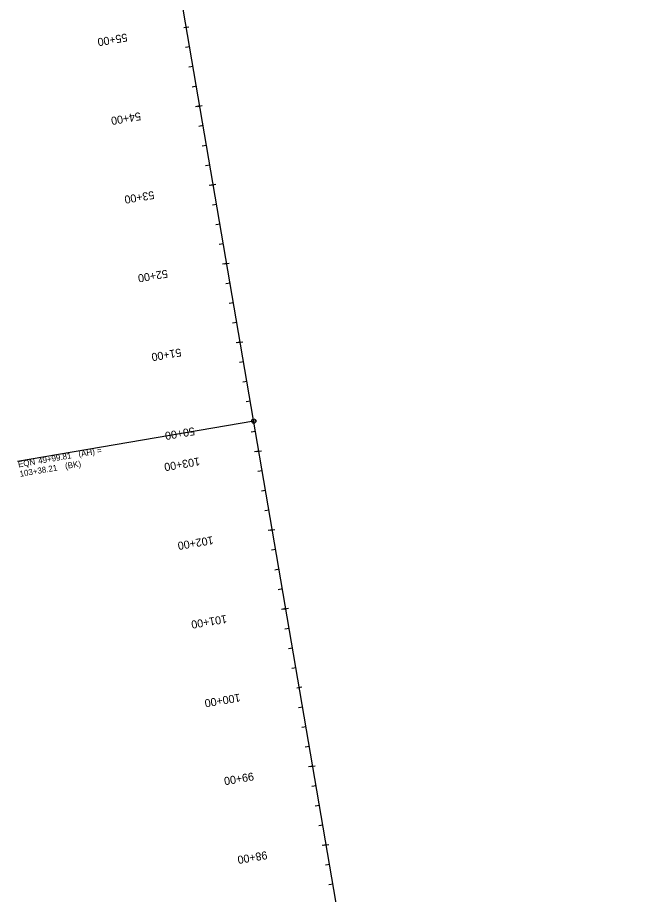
# Model space of a CAD drawing. Extents: x 11526371 to 11527168, y 9590726 to 9599509.
# Drawn here: x 11526394 to 11527166, y 9592932 to 9594030 of the extents above; entities that cross this region are included whole.
import ezdxf

# ---------------------------------------------------------------- set-up
doc = ezdxf.new("R2010")
doc.units = 0
for name, color, linetype in [('Alignment', 7, 'Continuous'), ('TextAlignment', 7, 'Continuous'), ('TextAlignmentLrg', 7, 'Continuous'), ('TextAlignmentSml', 7, 'Continuous')]:
    doc.layers.add(name, color=color, linetype=linetype)

msp = doc.modelspace()

# ---------------------------------------------------------------- linework, layer by layer
at = {"layer": 'Alignment'}
msp.add_line((11527165.7, 9590741), (11526539.8, 9594397.6), dxfattribs=at)
at = {"layer": 'TextAlignment'}
msp.add_line((11526689.3, 9593524.6), (11526393.6, 9593473.9), dxfattribs=at)
msp.add_circle((11526689.3, 9593524.6), 2.67, dxfattribs=at)
at = {"layer": 'TextAlignmentLrg'}
for p, q in [((11526601.8, 9594017.1), (11526607.9, 9594018.1)), ((11526621.7, 9593919), (11526616.4, 9593918.1)), ((11526638.6, 9593820.4), (11526633.2, 9593819.5)), ((11526655.5, 9593721.9), (11526650.1, 9593721)), ((11526672.3, 9593623.3), (11526667, 9593622.4)), ((11526686.2, 9593524.2), (11526692.2, 9593525.3)), ((11526695.7, 9593486.9), (11526690.3, 9593486)), ((11526712.6, 9593388.3), (11526707.2, 9593387.4)), ((11526729.4, 9593289.8), (11526724.1, 9593288.8)), ((11526743.3, 9593190.7), (11526749.3, 9593191.7)), ((11526763.2, 9593092.6), (11526757.8, 9593091.7)), ((11526780.1, 9592994.1), (11526774.7, 9592993.1))]:
    msp.add_line(p, q, dxfattribs=at)
at = {"layer": 'TextAlignmentSml'}
for p, q in [((11526601.8, 9594017.1), (11526607.9, 9594018.1)), ((11526609.1, 9593992.9), (11526603.7, 9593992)), ((11526613.3, 9593968.3), (11526607.9, 9593967.4)), ((11526617.5, 9593943.6), (11526612.1, 9593942.7)), ((11526618.7, 9593918.5), (11526624.7, 9593919.5)), ((11526626, 9593894.4), (11526620.6, 9593893.4)), ((11526630.2, 9593869.7), (11526624.8, 9593868.8)), ((11526634.4, 9593845.1), (11526629, 9593844.2)), ((11526635.6, 9593819.9), (11526641.6, 9593821)), ((11526642.8, 9593795.8), (11526637.4, 9593794.9)), ((11526647, 9593771.2), (11526641.7, 9593770.2)), ((11526651.3, 9593746.5), (11526645.9, 9593745.6)), ((11526652.5, 9593721.4), (11526658.5, 9593722.4)), ((11526659.7, 9593697.2), (11526654.3, 9593696.3)), ((11526663.9, 9593672.6), (11526658.5, 9593671.7)), ((11526668.1, 9593647.9), (11526662.7, 9593647)), ((11526669.3, 9593622.8), (11526675.4, 9593623.8)), ((11526676.6, 9593598.7), (11526671.2, 9593597.7)), ((11526680.8, 9593574), (11526675.4, 9593573.1)), ((11526685, 9593549.4), (11526679.6, 9593548.5)), ((11526686.2, 9593524.2), (11526692.2, 9593525.3)), ((11526691.5, 9593511.5), (11526686.1, 9593510.6)), ((11526692.7, 9593486.4), (11526698.7, 9593487.4)), ((11526699.9, 9593462.2), (11526694.5, 9593461.3)), ((11526704.1, 9593437.6), (11526698.8, 9593436.7)), ((11526708.4, 9593413), (11526703, 9593412)), ((11526709.6, 9593387.8), (11526715.6, 9593388.8)), ((11526716.8, 9593363.7), (11526711.4, 9593362.8)), ((11526721, 9593339), (11526715.6, 9593338.1)), ((11526725.2, 9593314.4), (11526719.8, 9593313.5)), ((11526726.4, 9593289.2), (11526732.5, 9593290.3)), ((11526733.7, 9593265.1), (11526728.3, 9593264.2)), ((11526737.9, 9593240.5), (11526732.5, 9593239.6)), ((11526742.1, 9593215.8), (11526736.7, 9593214.9)), ((11526743.3, 9593190.7), (11526749.3, 9593191.7)), ((11526750.5, 9593166.5), (11526745.2, 9593165.6)), ((11526754.8, 9593141.9), (11526749.4, 9593141)), ((11526759, 9593117.3), (11526753.6, 9593116.3)), ((11526760.2, 9593092.1), (11526766.2, 9593093.1)), ((11526767.4, 9593068), (11526762, 9593067.1)), ((11526771.6, 9593043.3), (11526766.2, 9593042.4)), ((11526775.8, 9593018.7), (11526770.5, 9593017.8)), ((11526777, 9592993.5), (11526783.1, 9592994.6)), ((11526784.3, 9592969.4), (11526778.9, 9592968.5)), ((11526788.5, 9592944.8), (11526783.1, 9592943.9))]:
    msp.add_line(p, q, dxfattribs=at)

# ---------------------------------------------------------------- texts
at = {"layer": 'TextAlignment'}
for s, p in [('(AH) = ', (11526470.5, 9593479.5)), ('EQN ', (11526394.8, 9593466.5)), ('49+99.81', (11526420, 9593470.9)), ('103+38.21', (11526396.8, 9593454.7)), ('(BK)', (11526453.7, 9593464.5))]:
    msp.add_text(s, height=7.5, rotation=9.7133, dxfattribs=at).set_placement(p)
at = {"layer": 'TextAlignmentLrg'}
for s, p in [('55+00', (11526530.1, 9594009.9)), ('50+00', (11526614.5, 9593517)), ('100+00', (11526671.5, 9593183.5))]:
    msp.add_text(s, height=10.02, rotation=189.7133, dxfattribs=at).set_placement(p)
at = {"layer": 'TextAlignmentSml'}
for s, p in [('55+00', (11526530.1, 9594009.9)), ('54+00', (11526547, 9593911.3)), ('53+00', (11526563.8, 9593812.7)), ('52+00', (11526580.7, 9593714.2)), ('51+00', (11526597.6, 9593615.6)), ('50+00', (11526614.5, 9593517)), ('103+00', (11526620.9, 9593479.2)), ('102+00', (11526637.8, 9593380.6)), ('101+00', (11526654.7, 9593282)), ('100+00', (11526671.5, 9593183.5)), ('99+00', (11526688.4, 9593084.9)), ('98+00', (11526705.3, 9592986.3))]:
    msp.add_text(s, height=10.02, rotation=189.7133, dxfattribs=at).set_placement(p)

doc.saveas('drawing.dxf')
